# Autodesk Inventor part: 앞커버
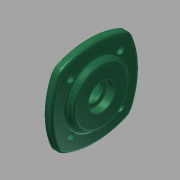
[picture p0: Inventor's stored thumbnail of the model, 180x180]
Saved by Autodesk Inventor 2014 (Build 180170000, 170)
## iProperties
Created: 2015-11
Part Number: 앞커버
Material: 일반
Document SubType Name: Modeling
Designer: mduedu
Density: 1 g/cm^3
Appearance: 매끄러움 - 짙은 바다 녹색
Mass: 112.857 g
Surface Area: 251.176 cm^2
Volume: 112.857 cm^3
Author: mduedu
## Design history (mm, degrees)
sketch "스케치1"
  geometry: L1 (50, 50)-(-50, 50); L2 (-50, 50)-(-50, -50); L3 (-50, -50)-(50, -50); L4 (50, -50)-(50, 50); L5 (0, 50)-(0, -50); L6 (50, 0)-(-50, 0); A1 r 90 centre (-40, 0) between (40.415, -40.415) and (40.415, 40.415); A2 r 90 centre (40, 0) between (-40.415, 40.415) and (-40.415, -40.415); A3 r 90 centre (0, -40) between (40.415, 40.415) and (-40.415, 40.415); A4 r 90 centre (0, 40) between (-40.415, -40.415) and (40.415, -40.415); 2 further points
  constraints: 12 end point, 8 point on circle, 5 midpoint, 4 centre point, 2 horizontal alignment, 2 parallel, 2 perpendicular, 2 symmetric about line, 2 tangent, 2 vertical alignment, 1 equal radius, 1 horizontal, 2 other
  dimensions: "d0" = 100 distance of L3.end L1.start; "d2" = 90 radius of A1
extrude "돌출1" new body sketch "스케치1" distance "d3" = 8; taper "d4" = 0 deg
sketch "스케치2"
  geometry: C1 r 35 at (0, 0); 1 further point
  constraints: 1 centre point, 1 coincident
  dimensions: "d5" = 70 diameter of C1
extrude "돌출2" join sketch "스케치2" distance "d6" = 7; taper "d7" = -30 deg
sketch "스케치3"
  geometry: L1 (0, 0)-(0, 40); L2 (0, 0)-(-28.284, 28.284); A1 r 40 centre (0, 0) between (0, 40) and (-28.284, 28.284); 2 further points
  constraints: 4 end point, 2 coincident, 2 point on circle, 1 centre point, 1 vertical
  dimensions: "d8" = 80 diameter of A1; "d9" = 45 deg angle of L1 L2
hole "구멍1" sketch "스케치3" at (-28.284, 28.284) diameter "d11" = 4.5; stored, may be unused: countersink angle "d15" = 90 deg, drill point angle "d17" = 118 deg; dims "d12" = 6, "d13" = 8, "d14" = 4.4, "d16" = 8
sketch "스케치4"
  geometry: C1 r 35 at (0, 0); 1 further point
  constraints: 1 centre point, 1 coincident
  dimensions: "d21" = 70 diameter of C1
extrude "돌출3" join sketch "스케치4" distance "d23" = 12; taper "d24" = 0 deg
hole "구멍2" diameter "d27" = 30; stored, may be unused: countersink angle "d31" = 90 deg, drill point angle "d33" = 0 deg; dims "d25" = 10, "d26" = 10, "d28" = 6, "d29" = 40, "d30" = 12, "d32" = 15
fillet "모깎기2" dims "d35" = 15
fillet "모깎기3" dims "d36" = 3
fillet "모깎기4" dims "d37" = 3
fillet "모깎기5" dims "d38" = 0.3
chamfer "모따기1" distance "d39" = 1; stored, may be unused: second distance "d40" = 2, angle "d41" = 45 deg
hole "구멍3" diameter "d44" = 20; stored, may be unused: countersink angle "d48" = 90 deg, drill point angle "d50" = 118 deg; dims "d45" = 6, "d46" = 30, "d47" = 8.7, "d49" = 8, "d55" = 10, "d56" = 10
fillet "모깎기6" dims "d51" = 0.3
chamfer "모따기2" distance "d52" = 0.7; stored, may be unused: second distance "d53" = 2, angle "d54" = 30 deg
node "솔리드1"
pattern_circular "원형 패턴1" dims angle "d19" = 360 deg
